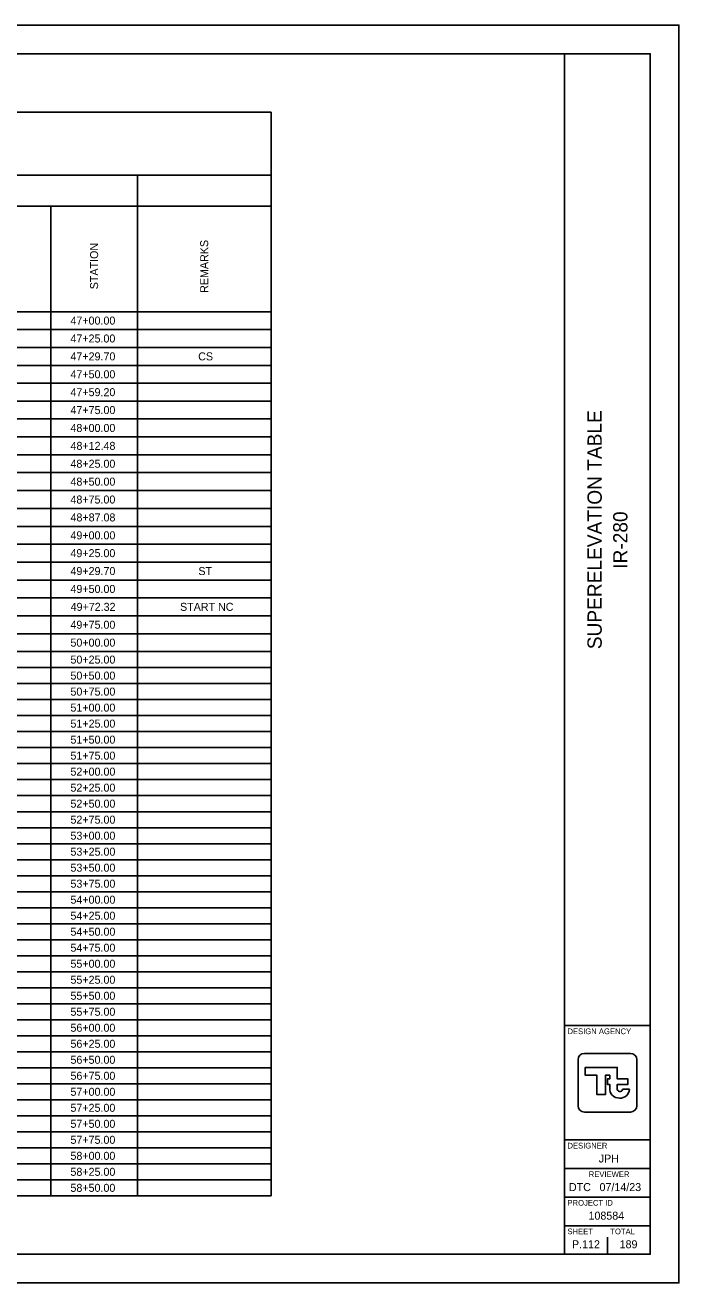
# Model space of a CAD drawing. Extents: x 0 to 34, y 0 to 22.
# Drawn here: x 22.56 to 34, y 0 to 22 of the extents above; entities that cross this region are included whole.
import ezdxf

# ---------------------------------------------------------------- set-up
doc = ezdxf.new("R2010")
doc.units = 0
for name, color, linetype in [('Default', 7, 'Continuous'), ('SH_Border', 7, 'Continuous'), ('SH_Cut_Line', 7, 'Continuous'), ('SH_Data', 7, 'Continuous')]:
    doc.layers.add(name, color=color, linetype=linetype)

msp = doc.modelspace()

# ---------------------------------------------------------------- linework, layer by layer
at = {"layer": 'Default'}
for p, q in [((6.635, 20.48), (26.861, 20.48)), ((26.861, 20.48), (26.861, 1.522)), ((6.635, 19.376), (26.861, 19.376)), ((24.522, 19.376), (24.522, 1.522)), ((6.635, 18.833), (26.861, 18.833)), ((23.007, 18.833), (23.007, 1.522)), ((6.635, 16.988), (26.861, 16.988)), ((6.635, 16.675), (26.861, 16.675)), ((6.635, 16.362), (26.861, 16.362)), ((6.635, 16.049), (26.861, 16.049)), ((6.635, 15.736), (26.861, 15.736)), ((6.635, 15.424), (26.861, 15.424)), ((6.635, 15.111), (26.861, 15.111)), ((6.635, 14.798), (26.861, 14.798)), ((6.635, 14.485), (26.861, 14.485)), ((6.635, 14.172), (26.861, 14.172)), ((6.635, 13.859), (26.861, 13.859)), ((6.635, 13.546), (26.861, 13.546)), ((6.635, 13.233), (26.861, 13.233)), ((6.635, 12.92), (26.861, 12.92)), ((6.635, 12.607), (26.861, 12.607)), ((6.635, 12.294), (26.861, 12.294)), ((6.635, 11.981), (26.861, 11.981)), ((6.635, 11.668), (26.861, 11.668)), ((6.635, 11.355), (26.861, 11.355)), ((6.635, 11.042), (26.861, 11.042)), ((6.635, 10.762), (26.861, 10.762)), ((6.635, 10.482), (26.861, 10.482)), ((6.635, 10.202), (26.861, 10.202)), ((6.635, 9.922), (26.861, 9.922)), ((6.635, 9.642), (26.861, 9.642)), ((6.635, 9.362), (26.861, 9.362)), ((6.635, 9.082), (26.861, 9.082)), ((6.635, 8.802), (26.861, 8.802)), ((6.635, 8.522), (26.861, 8.522)), ((6.635, 8.242), (26.861, 8.242)), ((6.635, 7.962), (26.861, 7.962)), ((6.635, 7.682), (26.861, 7.682)), ((6.635, 7.402), (26.861, 7.402)), ((6.635, 7.122), (26.861, 7.122)), ((6.635, 6.842), (26.861, 6.842)), ((6.635, 6.562), (26.861, 6.562)), ((6.635, 6.282), (26.861, 6.282)), ((6.635, 6.002), (26.861, 6.002)), ((6.635, 5.722), (26.861, 5.722)), ((6.635, 5.442), (26.861, 5.442)), ((6.635, 5.162), (26.861, 5.162)), ((6.635, 4.882), (26.861, 4.882)), ((6.635, 4.602), (26.861, 4.602)), ((6.635, 4.322), (26.861, 4.322)), ((6.635, 4.042), (26.861, 4.042)), ((6.635, 3.762), (26.861, 3.762)), ((6.635, 3.482), (26.861, 3.482)), ((6.635, 3.202), (26.861, 3.202)), ((6.635, 2.922), (26.861, 2.922)), ((6.635, 2.642), (26.861, 2.642)), ((6.635, 2.362), (26.861, 2.362)), ((6.635, 2.082), (26.861, 2.082)), ((6.635, 1.802), (26.861, 1.802)), ((6.635, 1.522), (26.861, 1.522))]:
    msp.add_line(p, q, dxfattribs=at)
at = {"layer": 'SH_Border'}
for p, q in [((32, 0.5), (32, 21.5)), ((32, 4.5), (33.5, 4.5)), ((32, 2.5), (33.5, 2.5)), ((32, 2), (33.5, 2)), ((32, 1.5), (33.5, 1.5)), ((32, 1), (33.5, 1))]:
    msp.add_line(p, q, dxfattribs=at)
msp.add_lwpolyline([(1.5, 21.5), (33.5, 21.5), (33.5, 0.5), (1.5, 0.5)], close=True, dxfattribs=at)
at = {"layer": 'SH_Cut_Line'}
msp.add_lwpolyline([(0, 0), (34, 0), (34, 22), (0, 22)], close=True, dxfattribs=at)
at = {"layer": 'SH_Data'}
for p, q in [((32.75, 3.5), (32.75, 3.5)), ((32.791, 3.415), (32.791, 3.415)), ((33.136, 3.385), (33.015, 3.385)), ((32.375, 0.675), (32.375, 0.675)), ((32.75, 0.5), (32.75, 0.8))]:
    msp.add_line(p, q, dxfattribs=at)
for points in [[(32.348, 4.014), (33.152, 4.014)], [(32.236, 3.099), (32.236, 3.901)], [(32.922, 3.399), (32.922, 3.47), (33.107, 3.47), (33.107, 3.568), (32.922, 3.568), (32.922, 3.768), (32.361, 3.768), (32.361, 3.632), (32.566, 3.632), (32.566, 3.294), (32.715, 3.294), (32.715, 3.63), (32.79, 3.63), (32.79, 3.568), (32.748, 3.568), (32.748, 3.47), (32.79, 3.47), (32.79, 3.415), (32.791, 3.415)], [(33.264, 3.901), (33.264, 3.099)], [(33.152, 2.986), (32.348, 2.986)]]:
    msp.add_lwpolyline(points, dxfattribs=at)
for centre, radius, start, end in [((32.348, 3.901), 0.113, 90, 180), ((33.152, 3.901), 0.113, 360, 90), ((32.949, 3.392), 0.16, 171.8856, 274.8323), ((32.968, 3.392), 0.0473, 171.8856, 350.9243), ((32.976, 3.392), 0.16, 265.1677, 357.3201), ((32.348, 3.099), 0.113, 180, 270), ((33.152, 3.099), 0.113, 270, 360)]:
    msp.add_arc(centre, radius, start, end, dxfattribs=at)

# ---------------------------------------------------------------- texts
at = {"layer": 'Default'}
for s, p in [('STATION', (23.834, 17.38)), ('REMARKS', (25.761, 17.317))]:
    msp.add_text(s, height=0.14, rotation=90, dxfattribs=at).set_placement(p)
for s, p in [('47+00.00', (23.35, 16.762)), ('47+25.00', (23.35, 16.449)), ('47+29.70', (23.35, 16.136)), ('CS', (25.586, 16.136)), ('47+50.00', (23.35, 15.823)), ('47+59.20', (23.35, 15.51)), ('47+75.00', (23.35, 15.197)), ('48+00.00', (23.35, 14.884)), ('48+12.48', (23.351, 14.571)), ('48+25.00', (23.35, 14.258)), ('48+50.00', (23.35, 13.945)), ('48+75.00', (23.35, 13.632)), ('48+87.08', (23.351, 13.319)), ('49+00.00', (23.35, 13.006)), ('49+25.00', (23.35, 12.694)), ('49+29.70', (23.35, 12.381)), ('ST', (25.589, 12.381)), ('49+50.00', (23.35, 12.068)), ('49+72.32', (23.353, 11.755)), ('START NC', (25.268, 11.755)), ('49+75.00', (23.35, 11.442)), ('50+00.00', (23.35, 11.129)), ('50+25.00', (23.35, 10.832)), ('50+50.00', (23.35, 10.552)), ('50+75.00', (23.35, 10.272)), ('51+00.00', (23.35, 9.992)), ('51+25.00', (23.35, 9.712)), ('51+50.00', (23.35, 9.432)), ('51+75.00', (23.35, 9.152)), ('52+00.00', (23.35, 8.872)), ('52+25.00', (23.35, 8.592)), ('52+50.00', (23.35, 8.312)), ('52+75.00', (23.35, 8.032)), ('53+00.00', (23.35, 7.752)), ('53+25.00', (23.35, 7.472)), ('53+50.00', (23.35, 7.192)), ('53+75.00', (23.35, 6.912)), ('54+00.00', (23.35, 6.632)), ('54+25.00', (23.35, 6.352)), ('54+50.00', (23.35, 6.072)), ('54+75.00', (23.35, 5.792)), ('55+00.00', (23.35, 5.512)), ('55+25.00', (23.35, 5.232)), ('55+50.00', (23.35, 4.952)), ('55+75.00', (23.35, 4.672)), ('56+00.00', (23.35, 4.392)), ('56+25.00', (23.35, 4.112)), ('56+50.00', (23.35, 3.832)), ('56+75.00', (23.35, 3.552)), ('57+00.00', (23.35, 3.272)), ('57+25.00', (23.35, 2.992)), ('57+50.00', (23.35, 2.712)), ('57+75.00', (23.35, 2.432)), ('58+00.00', (23.35, 2.152)), ('58+25.00', (23.35, 1.872)), ('58+50.00', (23.35, 1.592))]:
    msp.add_text(s, height=0.14, dxfattribs=at).set_placement(p)
at = {"layer": 'SH_Data'}
for s, p in [('SUPERELEVATION TABLE', (32.65, 11.084)), ('IR-280', (33.1, 12.491))]:
    msp.add_text(s, height=0.25, rotation=90, dxfattribs=at).set_placement(p)
for s, height, p in [('DESIGN AGENCY', 0.1, (32.05, 4.35)), ('DESIGNER', 0.1, (32.05, 2.35)), ('JPH', 0.14, (32.598, 2.105)), ('REVIEWER', 0.1, (32.422, 1.85)), ('DTC', 0.14, (32.076, 1.605)), ('07/14/23', 0.14, (32.611, 1.605)), ('PROJECT ID', 0.1, (32.05, 1.35)), ('108584', 0.14, (32.418, 1.105)), ('SHEET', 0.1, (32.05, 0.85)), ('TOTAL', 0.1, (32.8, 0.85)), ('P.112', 0.14, (32.129, 0.605)), ('189', 0.14, (32.963, 0.605))]:
    msp.add_text(s, height=height, dxfattribs=at).set_placement(p)

doc.saveas('drawing.dxf')
